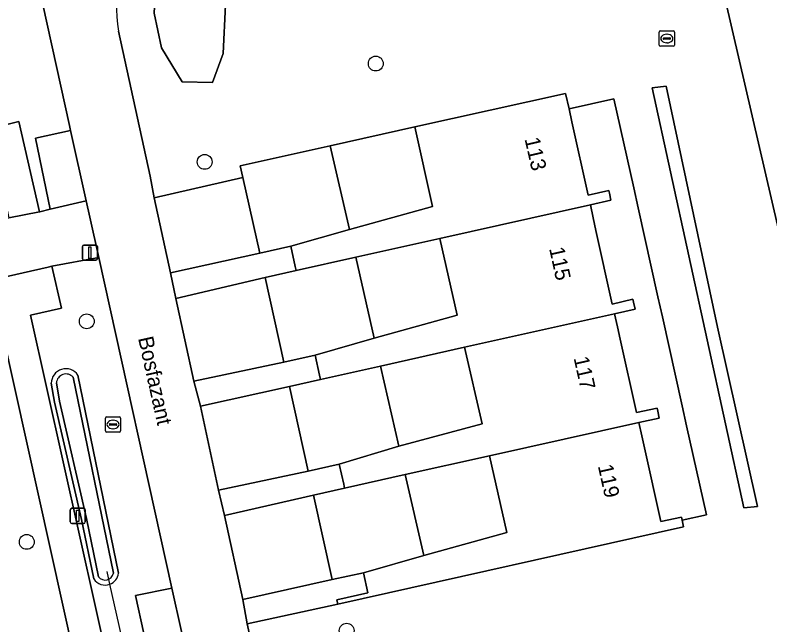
# Model space of a CAD drawing. Extents: x 156661 to 157576, y 383570 to 384425.
# Drawn here: x 156780.23 to 156829.98, y 383985.58 to 384025.77 of the extents above; entities that cross this region are included whole.
import ezdxf

# ---------------------------------------------------------------- set-up
doc = ezdxf.new("R2010")
doc.units = 0
for name, color, linetype in [('IMGEO_Boom', 7, 'Continuous'), ('IMGEO_Brandkraan', 7, 'Continuous'), ('IMGEO_Duiker', 7, 'Continuous'), ('IMGEO_Erf', 7, 'Continuous'), ('IMGEO_Groenvoorziening', 7, 'Continuous'), ('IMGEO_Haag', 7, 'Continuous'), ('IMGEO_Lichtmast', 7, 'Continuous'), ('IMGEO_Muur', 7, 'Continuous'), ('IMGEO_Oever', 7, 'Continuous'), ('IMGEO_Openbare_ruimte_label', 7, 'Continuous'), ('IMGEO_Pand', 7, 'Continuous'), ('IMGEO_Pand_nummerreeks', 7, 'Continuous'), ('IMGEO_Parkeervlak_open', 7, 'Continuous'), ('IMGEO_Rijbaan_lokaal_gesloten', 7, 'Continuous'), ('IMGEO_Rijbaan_lokaal_open', 7, 'Continuous'), ('IMGEO_Rioolput', 7, 'Continuous'), ('IMGEO_Voetpad_open', 7, 'Continuous'), ('IMGEO_Waterloop', 7, 'Continuous')]:
    doc.layers.add(name, color=color, linetype=linetype)

msp = doc.modelspace()

# ---------------------------------------------------------------- linework, layer by layer
at = {"layer": 'IMGEO_Boom'}
for centre in [(156804.007, 384022.575), (156792.725, 384016.096), (156784.955, 384005.588), (156781.002, 383991.046), (156802.09, 383985.2)]:
    msp.add_circle(centre, 0.489, dxfattribs=at)
at = {"layer": 'IMGEO_Brandkraan'}
for p, q in [((156786.186, 383998.359), (156786.186, 383999.211)), ((156786.261, 383999.285), (156787.113, 383999.285)), ((156786.674, 383999.065), (156786.699, 383999.065)), ((156787.187, 383999.211), (156787.187, 383998.359)), ((156786.445, 383998.779), (156786.445, 383998.791)), ((156786.883, 383998.742), (156786.485, 383998.742)), ((156786.488, 383998.828), (156786.886, 383998.828)), ((156786.929, 383998.791), (156786.929, 383998.779)), ((156787.113, 383998.285), (156786.261, 383998.285)), ((156786.697, 383998.505), (156786.672, 383998.505))]:
    msp.add_line(p, q, dxfattribs=at)
for points in [[(156786.186, 383998.359), (156786.186, 383999.211)], [(156786.261, 383999.285), (156787.113, 383999.285)], [(156787.187, 383999.211), (156787.187, 383998.359)], [(156787.113, 383998.285), (156786.261, 383998.285)]]:
    msp.add_lwpolyline(points, dxfattribs=at)
for centre, radius, start, end in [((156786.263, 383999.209), 0.0765, 91.552, 178.448), ((156786.263, 383999.209), 0.0765, 91.552, 178.448), ((156787.111, 383999.209), 0.0765, 1.552, 88.448), ((156787.111, 383999.209), 0.0765, 1.552, 88.448), ((156786.485, 383998.788), 0.0403, 85.8775, 175.7526), ((156786.482, 383998.778), 0.0366, 178.938, 274.7102), ((156786.886, 383998.785), 0.043, 264.8664, 352.4533), ((156786.89, 383998.79), 0.0386, 1.7309, 96.639), ((156786.263, 383998.361), 0.0765, 181.552, 268.448), ((156786.263, 383998.361), 0.0765, 181.552, 268.448), ((156787.111, 383998.361), 0.0765, 271.552, 358.448), ((156787.111, 383998.361), 0.0765, 271.552, 358.448)]:
    msp.add_arc(centre, radius, start, end, dxfattribs=at)
for centre, major_axis, ratio, start_param, end_param in [((156786.673, 383998.785), (-0.387, 0.002), 0.722429, 4.712389, 7.853982), ((156786.698, 383998.785), (-0.39, 0.002), 0.717154, 1.570796, 4.712389)]:
    msp.add_ellipse(centre, major_axis=major_axis, ratio=ratio, start_param=start_param, end_param=end_param, dxfattribs=at)
at = {"layer": 'IMGEO_Duiker'}
msp.add_lwpolyline([(156789.693, 383974.016), (156789.506, 383974.844), (156788.201, 383980.63), (156787.859, 383982.142), (156786.48, 383988.253), (156786.291, 383989.092)], dxfattribs=at)
at = {"layer": 'IMGEO_Erf'}
for points in [[(156819.704, 384020.241), (156816.745, 384019.584), (156816.932, 384018.741), (156818.005, 384013.904), (156819.361, 384014.209), (156819.402, 384014.025), (156819.506, 384013.565), (156818.15, 384013.26), (156818.34, 384012.398), (156818.52, 384011.579), (156819.589, 384006.726), (156820.943, 384007.039), (156820.99, 384006.839), (156821.093, 384006.392), (156819.738, 384006.079), (156819.929, 384005.226), (156820.112, 384004.408), (156821.194, 383999.569), (156822.553, 383999.863), (156822.596, 383999.664), (156822.694, 383999.211), (156821.335, 383998.916), (156821.531, 383998.039), (156821.709, 383997.239), (156822.792, 383992.381), (156824.149, 383992.68), (156824.192, 383992.487), (156825.795, 383992.829), (156824.491, 383998.697), (156824.197, 384000.019), (156822.894, 384005.885), (156822.602, 384007.197), (156821.3, 384013.056), (156821.006, 384014.382)], [(156802.262, 384011.647), (156807.742, 384013.163), (156806.578, 384018.405), (156801.005, 384017.154)], [(156803.899, 384004.477), (156809.378, 384005.992), (156808.226, 384011.043), (156802.683, 384009.805)], [(156805.523, 383997.362), (156811.011, 383998.838), (156809.862, 384003.873), (156804.319, 384002.634)], [(156807.168, 383990.152), (156812.648, 383991.667), (156811.495, 383996.718), (156805.952, 383995.48)]]:
    msp.add_lwpolyline(points, close=True, dxfattribs=at)
at = {"layer": 'IMGEO_Groenvoorziening'}
for points in [[(156853.18, 383919.265), (156854.491, 383919.448), (156860.158, 383919.98), (156825.282, 384070.084), (156817.43, 384068.287), (156851.989, 383919.079)], [(156851.989, 383919.079), (156817.43, 384068.287)], [(156783.368, 384036.038), (156781.019, 384037.168), (156777.266, 384038.543), (156775.643, 384044.434), (156772.725, 384043.785), (156778.442, 384018.254), (156780.475, 384018.747), (156781.838, 384012.804), (156781.864, 384012.809), (156782.553, 384012.974), (156781.573, 384017.661), (156783.89, 384018.153), (156783.818, 384018.482), (156781.479, 384029.084)], [(156787.052, 384024.701), (156789.126, 384015.149), (156789.406, 384013.718), (156795.246, 384015.063), (156795.075, 384015.834), (156801.005, 384017.154), (156806.578, 384018.405), (156816.517, 384020.612), (156816.745, 384019.584), (156819.704, 384020.241), (156821.006, 384014.382), (156821.3, 384013.056), (156822.602, 384007.197), (156822.894, 384005.885), (156824.197, 384000.019), (156824.491, 383998.697), (156825.795, 383992.829), (156824.192, 383992.487), (156824.29, 383992.04), (156801.499, 383986.949), (156795.536, 383985.651), (156797.01, 383979.104)], [(156762.934, 383934.118), (156793.6, 383940.758), (156778.599, 384008.292)], [(156784.373, 384002.045), (156787.054, 383988.983)], [(156785.412, 383988.609), (156784.605, 383992.525), (156782.818, 384000.264), (156782.615, 384001.501)]]:
    msp.add_lwpolyline(points, dxfattribs=at)
for points in [[(156790.598, 384029.417), (156791.891, 384029.688), (156793.423, 384029.076), (156794.108, 384026.454), (156793.947, 384023.239), (156793.236, 384021.317), (156791.242, 384021.378), (156789.878, 384023.621), (156789.39, 384025.897), (156789.52, 384028.323)], [(156791.891, 384029.688), (156790.598, 384029.417), (156789.52, 384028.323), (156789.39, 384025.897), (156789.878, 384023.621), (156791.242, 384021.378), (156793.236, 384021.317), (156793.947, 384023.239), (156794.108, 384026.454), (156793.423, 384029.076)], [(156829.172, 383993.391), (156826.526, 384005.203), (156823.136, 384021.095), (156822.221, 384020.978), (156828.257, 383993.293)], [(156822.221, 384020.978), (156823.136, 384021.095), (156826.526, 384005.203), (156829.172, 383993.391), (156828.257, 383993.293)], [(156785.743, 384009.788), (156782.661, 384009.212), (156783.294, 384006.453), (156781.235, 384006.002), (156786.625, 383981.827), (156787.859, 383982.142), (156789.272, 383982.501), (156788.165, 383987.516), (156790.572, 383987.99)]]:
    msp.add_lwpolyline(points, close=True, dxfattribs=at)
for centre, radius, start, end in [((156796.72, 384026.409), 9.817, 103.1994, 190.0187), ((156783.581, 384001.492), 0.966, 34.8992, 179.4894), ((156786.166, 383989.091), 0.895, 212.584, 290.5461), ((156786.164, 383989.092), 0.896, 290.6244, 353.0196)]:
    msp.add_arc(centre, radius, start, end, dxfattribs=at)
at = {"layer": 'IMGEO_Haag'}
msp.add_lwpolyline([(156829.172, 383993.391), (156826.526, 384005.203), (156823.136, 384021.095), (156822.221, 384020.978), (156828.257, 383993.293)], close=True, dxfattribs=at)
at = {"layer": 'IMGEO_Lichtmast'}
for p, q in [((156784.663, 384009.712), (156784.663, 384010.512)), ((156784.663, 384010.512), (156784.663, 384009.712)), ((156784.763, 384010.612), (156785.553, 384010.612)), ((156785.553, 384010.612), (156784.763, 384010.612)), ((156785.653, 384010.512), (156785.653, 384009.712)), ((156785.653, 384009.712), (156785.653, 384010.512)), ((156785.553, 384009.612), (156784.763, 384009.612)), ((156784.763, 384009.612), (156785.553, 384009.612)), ((156783.866, 383992.363), (156783.866, 383993.163)), ((156783.866, 383993.163), (156783.866, 383992.363)), ((156783.966, 383993.263), (156784.756, 383993.263)), ((156784.756, 383993.263), (156783.966, 383993.263)), ((156784.856, 383993.163), (156784.856, 383992.363)), ((156784.856, 383992.363), (156784.856, 383993.163)), ((156784.756, 383992.263), (156783.966, 383992.263)), ((156783.966, 383992.263), (156784.756, 383992.263))]:
    msp.add_line(p, q, dxfattribs=at)
for points in [[(156785.083, 384010.487), (156785.233, 384010.487), (156785.233, 384009.737), (156785.083, 384009.737), (156785.083, 384010.487)], [(156784.286, 383993.138), (156784.436, 383993.138), (156784.436, 383992.388), (156784.286, 383992.388), (156784.286, 383993.138)]]:
    msp.add_lwpolyline(points, dxfattribs=at)
for centre, start, end in [((156784.763, 384010.512), 90, 180), ((156784.763, 384010.512), 90, 180), ((156785.553, 384010.512), 0, 90), ((156785.553, 384010.512), 360, 90), ((156784.763, 384009.712), 180, 270), ((156784.763, 384009.712), 180, 270), ((156785.553, 384009.712), 270, 0), ((156785.553, 384009.712), 270, 0), ((156783.966, 383993.163), 90, 180), ((156783.966, 383993.163), 90, 180), ((156784.756, 383993.163), 0, 90), ((156784.756, 383993.163), 360, 90), ((156783.966, 383992.363), 180, 270), ((156783.966, 383992.363), 180, 270), ((156784.756, 383992.363), 270, 0), ((156784.756, 383992.363), 270, 0)]:
    msp.add_arc(centre, 0.1, start, end, dxfattribs=at)
at = {"layer": 'IMGEO_Muur'}
for points in [[(156816.745, 384019.584), (156819.704, 384020.241), (156821.006, 384014.382)], [(156806.578, 384018.405), (156801.005, 384017.154)], [(156821.3, 384013.056), (156822.602, 384007.197)], [(156822.894, 384005.885), (156824.197, 384000.019)], [(156824.491, 383998.697), (156825.795, 383992.829), (156824.192, 383992.487)]]:
    msp.add_lwpolyline(points, dxfattribs=at)
at = {"layer": 'IMGEO_Oever'}
for points in [[(156787.054, 383988.983), (156784.373, 384002.045)], [(156785.732, 383988.747), (156784.938, 383992.598), (156783.153, 384000.33), (156782.957, 384001.524)], [(156784.054, 384001.9), (156786.707, 383988.976)], [(156782.615, 384001.501), (156782.818, 384000.264), (156784.605, 383992.525), (156785.412, 383988.609)]]:
    msp.add_lwpolyline(points, dxfattribs=at)
for centre, radius, start, end in [((156783.581, 384001.492), 0.966, 34.8992, 179.4894), ((156783.581, 384001.493), 0.624, 40.703, 177.1356), ((156786.166, 383989.091), 0.895, 212.584, 290.5461), ((156786.169, 383989.078), 0.548, 217.1783, 349.2569), ((156786.164, 383989.092), 0.896, 290.6244, 353.0196)]:
    msp.add_arc(centre, radius, start, end, dxfattribs=at)
at = {"layer": 'IMGEO_Pand'}
for points in [[(156818.15, 384013.26), (156819.506, 384013.565), (156819.402, 384014.025), (156819.361, 384014.209), (156818.005, 384013.904), (156816.932, 384018.741), (156816.745, 384019.584), (156816.517, 384020.612), (156806.578, 384018.405), (156807.742, 384013.163), (156802.262, 384011.647), (156798.406, 384010.53), (156798.701, 384009.202), (156798.762, 384008.929), (156802.683, 384009.805), (156808.226, 384011.043)], [(156798.406, 384010.53), (156802.262, 384011.647), (156801.005, 384017.154), (156795.075, 384015.834), (156795.246, 384015.063), (156796.356, 384010.074)], [(156819.738, 384006.079), (156821.093, 384006.392), (156820.99, 384006.839), (156820.943, 384007.039), (156819.589, 384006.726), (156818.52, 384011.579), (156818.34, 384012.398), (156818.15, 384013.26), (156808.226, 384011.043), (156809.378, 384005.992), (156803.899, 384004.477), (156800.002, 384003.354), (156800.297, 384002.026), (156800.358, 384001.75), (156804.319, 384002.634), (156809.862, 384003.873)], [(156802.683, 384009.805), (156798.762, 384008.929), (156796.712, 384008.471), (156797.952, 384002.898), (156800.002, 384003.354), (156803.899, 384004.477)], [(156821.335, 383998.916), (156822.694, 383999.211), (156822.596, 383999.664), (156822.553, 383999.863), (156821.194, 383999.569), (156820.112, 384004.408), (156819.929, 384005.226), (156819.738, 384006.079), (156809.862, 384003.873), (156811.011, 383998.838), (156805.523, 383997.362), (156801.599, 383996.174), (156801.894, 383994.847), (156801.952, 383994.586), (156805.952, 383995.48), (156811.495, 383996.718)], [(156804.319, 384002.634), (156800.358, 384001.75), (156798.309, 384001.292), (156799.549, 383995.718), (156801.599, 383996.174), (156805.523, 383997.362)], [(156807.168, 383990.152), (156803.189, 383989.016), (156803.485, 383987.689), (156801.436, 383987.232), (156801.499, 383986.949), (156824.29, 383992.04), (156824.192, 383992.487), (156824.149, 383992.68), (156822.792, 383992.381), (156821.709, 383997.239), (156821.531, 383998.039), (156821.335, 383998.916), (156811.495, 383996.718), (156812.648, 383991.667)], [(156805.952, 383995.48), (156801.952, 383994.586), (156799.902, 383994.128), (156801.141, 383988.56), (156803.189, 383989.016), (156807.168, 383990.152)]]:
    msp.add_lwpolyline(points, close=True, dxfattribs=at)
at = {"layer": 'IMGEO_Parkeervlak_open'}
for points in [[(156783.89, 384018.153), (156781.573, 384017.661), (156782.553, 384012.974), (156784.912, 384013.537)], [(156795.246, 384015.063), (156789.406, 384013.718), (156790.471, 384008.784), (156796.356, 384010.074)], [(156796.712, 384008.471), (156790.816, 384007.092), (156792.018, 384001.647), (156797.952, 384002.898)], [(156798.309, 384001.292), (156792.461, 383999.986), (156793.634, 383994.464), (156799.549, 383995.718)], [(156799.902, 383994.128), (156794.036, 383992.786), (156795.233, 383987.245), (156801.141, 383988.56)], [(156793.102, 383976.569), (156790.572, 383987.99), (156788.165, 383987.516), (156789.272, 383982.501), (156789.615, 383980.975), (156790.698, 383976.013)]]:
    msp.add_lwpolyline(points, close=True, dxfattribs=at)
at = {"layer": 'IMGEO_Rijbaan_lokaal_gesloten'}
msp.add_lwpolyline([(156778.599, 384008.292), (156782.408, 384009.165), (156782.661, 384009.212), (156785.743, 384009.788), (156785.155, 384012.442), (156784.912, 384013.537), (156782.553, 384012.974), (156781.864, 384012.809), (156781.838, 384012.804), (156779.821, 384012.399), (156779.792, 384012.393), (156777.107, 384012.058), (156766.184, 384009.37), (156767.319, 383999.798), (156772.355, 384000.925), (156771.991, 384002.639), (156771.942, 384003.438)], dxfattribs=at)
at = {"layer": 'IMGEO_Rijbaan_lokaal_open'}
for points in [[(156781.479, 384029.084), (156783.818, 384018.482), (156783.89, 384018.153), (156784.912, 384013.537), (156785.155, 384012.442), (156785.743, 384009.788), (156790.572, 383987.99), (156793.102, 383976.569), (156795.252, 383966.882), (156795.637, 383965.148), (156800.028, 383945.365), (156801.949, 383936.722), (156802.676, 383933.449), (156808.224, 383908.678)], [(156803.072, 383952.198), (156801.882, 383957.669), (156801.484, 383959.425), (156800.258, 383964.867), (156799.852, 383966.521), (156798.681, 383972.018), (156798.285, 383973.693), (156797.01, 383979.104), (156795.536, 383985.651), (156795.233, 383987.245), (156794.036, 383992.786), (156793.634, 383994.464), (156792.461, 383999.986), (156792.018, 384001.647), (156790.816, 384007.092), (156790.471, 384008.784), (156789.406, 384013.718), (156789.126, 384015.149), (156787.052, 384024.701)]]:
    msp.add_lwpolyline(points, dxfattribs=at)
msp.add_arc((156796.72, 384026.409), 9.817, 103.1994, 190.0187, dxfattribs=at)
at = {"layer": 'IMGEO_Rioolput'}
for p, q in [((156822.691, 384023.796), (156822.691, 384024.648)), ((156822.766, 384024.722), (156823.618, 384024.722)), ((156823.179, 384024.502), (156823.204, 384024.502)), ((156823.692, 384024.648), (156823.692, 384023.796)), ((156822.95, 384024.216), (156822.95, 384024.228)), ((156823.388, 384024.179), (156822.99, 384024.179)), ((156822.993, 384024.265), (156823.391, 384024.265)), ((156823.202, 384023.942), (156823.177, 384023.942)), ((156823.434, 384024.228), (156823.434, 384024.216)), ((156823.618, 384023.722), (156822.766, 384023.722))]:
    msp.add_line(p, q, dxfattribs=at)
for points in [[(156822.691, 384023.796), (156822.691, 384024.648)], [(156822.766, 384024.722), (156823.618, 384024.722)], [(156823.692, 384024.648), (156823.692, 384023.796)], [(156823.618, 384023.722), (156822.766, 384023.722)]]:
    msp.add_lwpolyline(points, dxfattribs=at)
for centre, radius, start, end in [((156822.768, 384024.646), 0.0765, 91.552, 178.448), ((156822.768, 384024.646), 0.0765, 91.552, 178.448), ((156823.616, 384024.646), 0.0765, 1.552, 88.448), ((156823.616, 384024.646), 0.0765, 1.552, 88.448), ((156822.99, 384024.225), 0.0403, 85.8775, 175.7526), ((156822.987, 384024.215), 0.0366, 178.938, 274.7102), ((156823.391, 384024.222), 0.043, 264.8664, 352.4533), ((156823.395, 384024.227), 0.0386, 1.7309, 96.639), ((156822.768, 384023.798), 0.0765, 181.552, 268.448), ((156822.768, 384023.798), 0.0765, 181.552, 268.448), ((156823.616, 384023.798), 0.0765, 271.552, 358.448), ((156823.616, 384023.798), 0.0765, 271.552, 358.448)]:
    msp.add_arc(centre, radius, start, end, dxfattribs=at)
for centre, major_axis, ratio, start_param, end_param in [((156823.178, 384024.222), (-0.387, 0.002), 0.722429, 4.712389, 7.853982), ((156823.203, 384024.222), (-0.39, 0.002), 0.717154, 1.570796, 4.712389)]:
    msp.add_ellipse(centre, major_axis=major_axis, ratio=ratio, start_param=start_param, end_param=end_param, dxfattribs=at)
at = {"layer": 'IMGEO_Voetpad_open'}
for points in [[(156772.725, 384043.785), (156770.782, 384043.37), (156774.397, 384027.214), (156774.72, 384025.769), (156776.934, 384015.874), (156778.942, 384016.363), (156779.821, 384012.399), (156781.838, 384012.804), (156780.475, 384018.747), (156778.442, 384018.254)], [(156798.762, 384008.929), (156798.701, 384009.202), (156798.406, 384010.53), (156796.356, 384010.074), (156790.471, 384008.784), (156790.816, 384007.092), (156796.712, 384008.471)], [(156781.235, 384006.002), (156783.294, 384006.453), (156782.661, 384009.212), (156782.408, 384009.165), (156778.599, 384008.292), (156793.6, 383940.758), (156795.59, 383941.189), (156786.905, 383980.313), (156788.201, 383980.63), (156789.615, 383980.975), (156789.272, 383982.501), (156787.859, 383982.142), (156786.625, 383981.827)], [(156800.358, 384001.75), (156800.297, 384002.026), (156800.002, 384003.354), (156797.952, 384002.898), (156792.018, 384001.647), (156792.461, 383999.986), (156798.309, 384001.292)], [(156801.952, 383994.586), (156801.894, 383994.847), (156801.599, 383996.174), (156799.549, 383995.718), (156793.634, 383994.464), (156794.036, 383992.786), (156799.902, 383994.128)], [(156803.189, 383989.016), (156801.141, 383988.56), (156795.233, 383987.245), (156795.536, 383985.651), (156801.499, 383986.949), (156801.436, 383987.232), (156803.485, 383987.689)]]:
    msp.add_lwpolyline(points, close=True, dxfattribs=at)
at = {"layer": 'IMGEO_Waterloop'}
for points in [[(156782.957, 384001.524), (156783.153, 384000.33), (156784.938, 383992.598), (156785.732, 383988.747)], [(156786.707, 383988.976), (156784.054, 384001.9)]]:
    msp.add_lwpolyline(points, dxfattribs=at)
for centre, radius, start, end in [((156783.581, 384001.493), 0.624, 40.703, 177.1356), ((156786.169, 383989.078), 0.548, 217.1783, 349.2569)]:
    msp.add_arc(centre, radius, start, end, dxfattribs=at)

# ---------------------------------------------------------------- texts
at = {"layer": 'IMGEO_Openbare_ruimte_label'}
msp.add_text('Bosfazant', height=1, rotation=282.535, dxfattribs=at).set_placement((156788.332, 384004.476))
at = {"layer": 'IMGEO_Pand_nummerreeks'}
for s, rotation, p in [('113', 283.0117, (156813.805, 384017.605)), ('115', 282.4444, (156815.427, 384010.383)), ('117', 282.6679, (156817.04, 384003.167)), ('119', 282.6364, (156818.636, 383996.052))]:
    msp.add_text(s, height=1, rotation=rotation, dxfattribs=at).set_placement(p)

doc.saveas('drawing.dxf')
